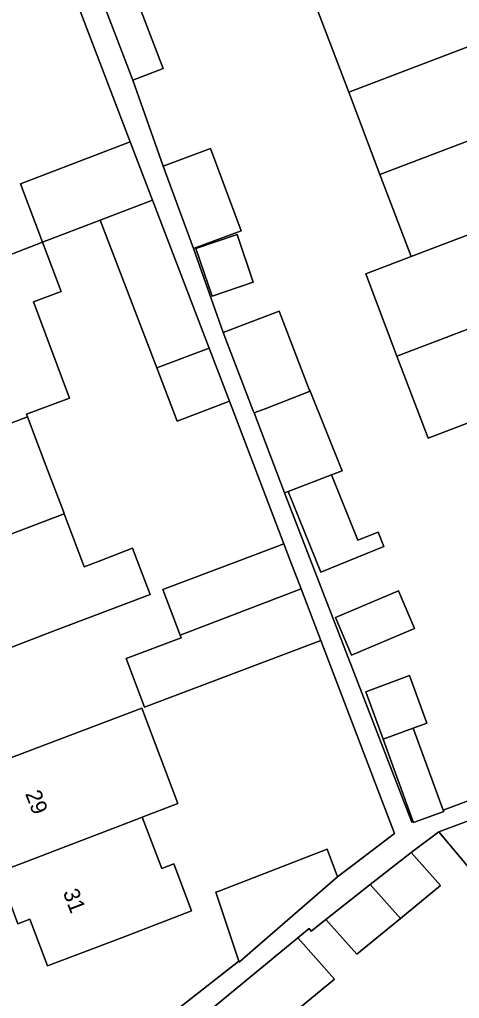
# Model space of a CAD drawing. Extents: x 159960 to 160866, y 382700 to 383354.
# Drawn here: x 160388.9 to 160416.4, y 382972.6 to 383033.8 of the extents above; entities that cross this region are included whole.
import ezdxf

# ---------------------------------------------------------------- set-up
doc = ezdxf.new("R2010")
doc.units = 0
for name, color, linetype in [('IMGEO_Erf', 7, 'Continuous'), ('IMGEO_Pand', 7, 'Continuous'), ('IMGEO_Pand_nummerreeks', 7, 'Continuous'), ('IMGEO_Voetpad_open', 7, 'Continuous')]:
    doc.layers.add(name, color=color, linetype=linetype)

msp = doc.modelspace()

# ---------------------------------------------------------------- linework, layer by layer
at = {"layer": 'IMGEO_Erf'}
for points in [[(160395.799, 383026.145), (160391.558, 383037.224)], [(160395.905, 383035.84), (160397.867, 383030.712), (160395.972, 383029.993), (160397.856, 383024.615), (160400.828, 383025.717), (160402.73, 383020.586), (160399.759, 383019.484), (160401.621, 383014.237), (160405.112, 383015.574), (160406.986, 383010.679), (160407.06, 383010.558), (160409.066, 383005.597), (160408.389, 383005.34), (160410.04, 383001.259), (160411.303, 383001.77), (160411.666, 383000.872), (160407.714, 382999.273), (160405.676, 383004.311), (160405.455, 383004.227), (160413.406, 382983.643), (160413.493, 382983.676), (160411.611, 382988.83), (160410.532, 382991.784), (160413.262, 382992.804), (160414.348, 382989.83), (160413.506, 382989.523), (160415.381, 382984.388), (160422.831, 382987.197)], [(160417.268, 383008.708), (160414.425, 383007.629), (160412.477, 383012.763), (160410.53, 383017.897), (160413.368, 383018.974), (160411.418, 383024.107), (160409.468, 383029.24), (160407.518, 383034.373)], [(160396.434, 382970.151), (160402.596, 382974.961), (160401.162, 382979.268), (160401.401, 382979.36), (160408.128, 382981.961), (160408.757, 382980.238), (160412.338, 382982.941), (160407.722, 382995), (160396.695, 382990.829), (160395.545, 382993.869), (160398.99, 382995.161), (160398.927, 382995.327), (160397.849, 382998.178), (160402.665, 383000), (160405.41, 383001.039), (160402.003, 383009.943), (160398.734, 383008.691), (160397.462, 383012.015), (160393.927, 383021.246), (160390.322, 383019.864), (160388.946, 383023.521), (160389.368, 383023.683), (160395.799, 383026.145)], [(160417.58, 382980.088), (160415.092, 382983.053), (160413.377, 382981.749), (160415.214, 382979.698), (160412.705, 382977.638), (160409.981, 382975.4), (160408.037, 382977.571), (160407.113, 382976.848), (160406.991, 382976.996), (160406.283, 382976.414), (160408.583, 382973.846), (160400.752, 382967.413)]]:
    msp.add_lwpolyline(points, dxfattribs=at)
for points in [[(160403.49, 383017.368), (160400.916, 383016.499), (160399.911, 383019.475), (160402.485, 383020.345)], [(160390.322, 383019.864), (160391.476, 383016.797), (160389.74, 383016.147), (160392.007, 383010.14), (160389.318, 383009.122), (160389.381, 383008.956), (160390.526, 383005.93), (160391.617, 383003.047), (160391.672, 383002.903), (160392.77, 383000), (160392.92, 382999.604), (160393.961, 383000), (160395.939, 383000.753), (160396.226, 383000), (160397.037, 382997.869), (160391.156, 382995.63), (160386.48, 382993.859), (160384.136, 383000.05), (160381.845, 383006.102), (160379.5, 383012.294), (160384.177, 383014.064), (160385.807, 383014.674), (160384.67, 383017.696)], [(160412.576, 382998.096), (160413.573, 382995.749), (160409.634, 382994.075), (160408.637, 382996.422)], [(160390.681, 382988.554), (160396.528, 382990.766), (160398.782, 382984.807), (160396.556, 382983.965), (160397.772, 382980.758), (160398.53, 382981.045), (160399.642, 382978.111), (160398.886, 382977.82), (160395.307, 382976.443), (160390.63, 382974.674), (160389.528, 382977.587), (160388.772, 382977.301), (160387.555, 382980.518), (160386.339, 382983.734), (160387.055, 382984.005), (160386.004, 382986.785)]]:
    msp.add_lwpolyline(points, close=True, dxfattribs=at)
at = {"layer": 'IMGEO_Pand'}
for points in [[(160419.384, 383033.002), (160417.429, 383038.133), (160407.518, 383034.373), (160409.468, 383029.24)], [(160395.905, 383035.84), (160394.009, 383035.121), (160395.972, 383029.993), (160397.867, 383030.712)], [(160411.418, 383024.107), (160421.339, 383027.871), (160419.384, 383033.002), (160409.468, 383029.24)], [(160423.294, 383022.74), (160421.339, 383027.871), (160411.418, 383024.107), (160413.368, 383018.974)], [(160395.799, 383026.145), (160389.368, 383023.683), (160388.946, 383023.521), (160390.322, 383019.864), (160393.927, 383021.246), (160397.195, 383022.5)], [(160397.856, 383024.615), (160399.759, 383019.484), (160402.73, 383020.586), (160400.828, 383025.717)], [(160400.735, 383013.254), (160397.195, 383022.5), (160393.927, 383021.246), (160397.462, 383012.015)], [(160425.25, 383017.609), (160423.294, 383022.74), (160413.368, 383018.974), (160410.53, 383017.897), (160412.477, 383012.763)], [(160399.911, 383019.475), (160400.916, 383016.499), (160403.49, 383017.368), (160402.485, 383020.345)], [(160381.845, 383006.102), (160389.381, 383008.956), (160389.318, 383009.122), (160392.007, 383010.14), (160389.74, 383016.147), (160391.476, 383016.797), (160390.322, 383019.864), (160384.67, 383017.696), (160385.807, 383014.674), (160384.177, 383014.064), (160379.5, 383012.294)], [(160417.268, 383008.708), (160427.205, 383012.478), (160425.25, 383017.609), (160412.477, 383012.763), (160414.425, 383007.629)], [(160401.621, 383014.237), (160403.496, 383009.343), (160403.547, 383009.209), (160404.233, 383009.472), (160407.06, 383010.558), (160406.986, 383010.679), (160405.112, 383015.574)], [(160400.735, 383013.254), (160397.462, 383012.015), (160398.734, 383008.691), (160402.003, 383009.943)], [(160407.06, 383010.558), (160404.233, 383009.472), (160403.547, 383009.209), (160405.455, 383004.227), (160405.676, 383004.311), (160408.389, 383005.34), (160409.066, 383005.597)], [(160390.526, 383005.93), (160389.381, 383008.956), (160381.845, 383006.102), (160384.136, 383000.05), (160391.672, 383002.903), (160391.617, 383003.047)], [(160408.389, 383005.34), (160405.676, 383004.311), (160407.714, 382999.273), (160411.666, 383000.872), (160411.303, 383001.77), (160410.04, 383001.259)], [(160384.136, 383000.05), (160386.48, 382993.859), (160391.156, 382995.63), (160397.037, 382997.869), (160396.226, 383000), (160395.939, 383000.753), (160393.961, 383000), (160392.92, 382999.604), (160392.77, 383000), (160391.672, 383002.903)], [(160406.488, 382998.224), (160405.808, 383000), (160405.41, 383001.039), (160402.665, 383000), (160397.849, 382998.178), (160398.927, 382995.327)], [(160406.488, 382998.224), (160398.927, 382995.327), (160398.99, 382995.161), (160395.545, 382993.869), (160396.695, 382990.829), (160407.722, 382995)], [(160408.637, 382996.422), (160409.634, 382994.075), (160413.573, 382995.749), (160412.576, 382998.096)], [(160411.611, 382988.83), (160413.506, 382989.523), (160414.348, 382989.83), (160413.262, 382992.804), (160410.532, 382991.784)], [(160396.556, 382983.965), (160398.782, 382984.807), (160396.528, 382990.766), (160390.681, 382988.554), (160386.004, 382986.785), (160387.055, 382984.005), (160386.339, 382983.734), (160387.555, 382980.518), (160396.127, 382983.789)], [(160411.611, 382988.83), (160413.493, 382983.676), (160413.51, 382983.63), (160415.405, 382984.322), (160415.381, 382984.388), (160413.506, 382989.523)], [(160418.23, 382984.21), (160415.092, 382983.053), (160417.58, 382980.088), (160419.991, 382982.111)], [(160397.772, 382980.758), (160396.556, 382983.965), (160396.127, 382983.789), (160387.555, 382980.518), (160388.772, 382977.301), (160389.528, 382977.587), (160390.63, 382974.674), (160395.307, 382976.443), (160398.886, 382977.82), (160399.642, 382978.111), (160398.53, 382981.045)], [(160408.757, 382980.238), (160408.128, 382981.961), (160401.401, 382979.36), (160401.162, 382979.268), (160402.596, 382974.961), (160402.616, 382974.902), (160403.45, 382975.627)], [(160413.377, 382981.749), (160410.817, 382979.746), (160412.705, 382977.638), (160415.214, 382979.698)], [(160412.705, 382977.638), (160410.817, 382979.746), (160408.037, 382977.571), (160409.981, 382975.4)], [(160406.283, 382976.414), (160398.565, 382970.075), (160400.752, 382967.413), (160408.583, 382973.846)]]:
    msp.add_lwpolyline(points, close=True, dxfattribs=at)
at = {"layer": 'IMGEO_Voetpad_open'}
for points in [[(160391.558, 383037.224), (160395.799, 383026.145), (160397.195, 383022.5), (160400.735, 383013.254), (160402.003, 383009.943), (160405.41, 383001.039), (160405.808, 383000), (160406.488, 382998.224), (160407.722, 382995), (160412.338, 382982.941), (160408.757, 382980.238), (160403.45, 382975.627), (160402.616, 382974.902), (160402.596, 382974.961), (160396.434, 382970.151)], [(160422.831, 382987.197), (160415.381, 382984.388), (160415.405, 382984.322), (160413.51, 382983.63), (160413.493, 382983.676), (160413.406, 382983.643), (160405.455, 383004.227), (160403.547, 383009.209), (160403.496, 383009.343), (160401.621, 383014.237), (160399.759, 383019.484), (160397.856, 383024.615), (160395.972, 383029.993), (160394.009, 383035.121)], [(160398.565, 382970.075), (160406.283, 382976.414), (160406.991, 382976.996), (160407.113, 382976.848), (160408.037, 382977.571), (160410.817, 382979.746), (160413.377, 382981.749), (160415.092, 382983.053), (160418.23, 382984.21)]]:
    msp.add_lwpolyline(points, dxfattribs=at)

# ---------------------------------------------------------------- texts
at = {"layer": 'IMGEO_Pand_nummerreeks'}
for s, rotation, p in [('29', 290.9052, (160389.22, 382985.429)), ('31', 290.90702, (160391.574, 382979.268))]:
    msp.add_text(s, height=1, rotation=rotation, dxfattribs=at).set_placement(p)

doc.saveas('drawing.dxf')
